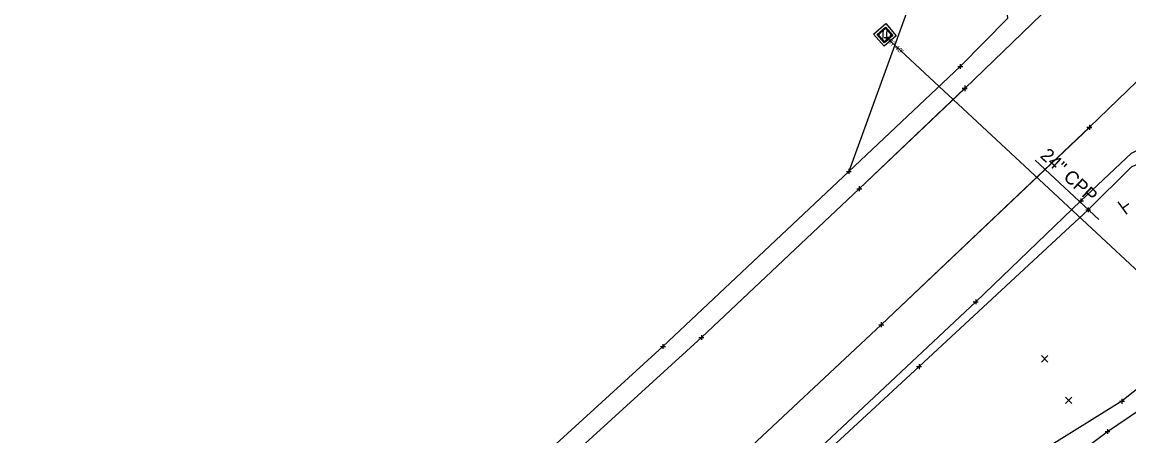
# Model space of a CAD drawing. Extents: x 236 to 155644, y 66 to 491728.
# Drawn here: x 147690.6 to 147919.6, y 487289.2 to 487374.8 of the extents above; entities that cross this region are included whole.
import ezdxf

# ---------------------------------------------------------------- set-up
doc = ezdxf.new("R2010")
doc.units = 0
for name, color, linetype in [('DR_X_Storm_Sewer', 7, 'Continuous'), ('DR_X_Text', 7, 'Continuous'), ('GE_X_Alignment', 7, 'Continuous'), ('PM_X_Edge_Line', 7, 'Continuous'), ('PV_X_EOP', 7, 'Continuous'), ('PV_X_Shoulder', 7, 'Continuous'), ('PV_X_Shoulder_Aggregate', 7, 'Continuous'), ('RD_X_Cells', 7, 'Continuous'), ('RD_X_RR_Cells', 7, 'Continuous'), ('RW_X_Esmt_LA', 7, 'Continuous'), ('SC_Scratch1', 7, 'Continuous'), ('SV_P_Mon_Cells_Set', 7, 'Continuous'), ('SV_X_Mon_Cells_Found', 7, 'Continuous'), ('SV_X_Shot_Marker', 7, 'Continuous'), ('SV_X_Terrain_Boundary', 7, 'Continuous')]:
    doc.layers.add(name, color=color, linetype=linetype)

msp = doc.modelspace()

# ---------------------------------------------------------------- linework, layer by layer
at = {"layer": 'DR_X_Storm_Sewer'}
msp.add_line((147869.46, 487371.63), (147938.02, 487307.8), dxfattribs=at)
at = {"layer": 'DR_X_Text'}
msp.add_line((147913.42, 487333.98), (147900.26, 487346.23), dxfattribs=at)
at = {"layer": 'GE_X_Alignment'}
for p, q in [((147919.29, 487335.04), (147917.38, 487337.61)), ((147918.34, 487336.32), (147919.62, 487337.28))]:
    msp.add_line(p, q, dxfattribs=at)
at = {"layer": 'PM_X_Edge_Line'}
for points in [[(147693.12, 487187.03), (147735.46, 487223.2), (147776.17, 487259.34), (147831.17, 487309.51), (147863.85, 487340.33), (147885.66, 487361.17)], [(147911.49, 487353.01), (147868.4, 487312.17), (147833.06, 487279.09), (147795.98, 487245.09), (147757.86, 487210.93), (147709.11, 487169.09)]]:
    msp.add_lwpolyline(points, dxfattribs=at)
at = {"layer": 'PV_X_EOP'}
for points in [[(147693.25, 487187.07), (147735.46, 487223.2), (147776.17, 487259.34), (147831.17, 487309.51), (147863.85, 487340.33), (147885.66, 487361.04), (147949.12, 487422.42), (147982.57, 487455.18), (148015.64, 487487.44), (148041.95, 487512.76)], [(148067.69, 487505.78), (148041.51, 487479.67), (148022.76, 487461.37), (148000.61, 487439.67), (147970.81, 487410.54), (147942.69, 487383.21), (147911.46, 487353.05), (147868.4, 487312.17), (147833.06, 487279.09), (147795.98, 487245.09), (147757.86, 487210.93), (147709.11, 487169.11)]]:
    msp.add_lwpolyline(points, dxfattribs=at)
at = {"layer": 'PV_X_Shoulder'}
for points in [[(147690.61, 487190.15), (147732.8, 487226.1), (147774.27, 487263.04), (147823.22, 487307.65), (147861.69, 487343.91), (147884.74, 487365.64), (147894.59, 487375.61), (147893.39, 487386.74), (147891.21, 487392.14), (147885.44, 487395.33), (147880.57, 487395.98)], [(147716.48, 487162.39), (147750.61, 487192.09), (147787.34, 487224.12), (147823.29, 487256.58), (147855.91, 487286.84), (147887.93, 487316.9), (147909.72, 487337.82), (147920.17, 487347.67), (147924.23, 487349.79), (147934.53, 487351.81), (147947.58, 487349.62), (147959.14, 487340.88), (147972.4, 487326.26), (147986.99, 487307.58), (147996.62, 487292.84), (148010.03, 487266.34), (148017.23, 487247.05)]]:
    msp.add_lwpolyline(points, dxfattribs=at)
at = {"layer": 'PV_X_Shoulder_Aggregate'}
msp.add_lwpolyline([(148012.53, 487250.31), (148003.26, 487274.09), (147989.7, 487297.58), (147980.31, 487311.09), (147966.57, 487328.17), (147956.32, 487337.98), (147948.04, 487345.7), (147936.67, 487349.15), (147928.99, 487348.9), (147920.13, 487344.77), (147911.2, 487335.96), (147876.2, 487303.5), (147840.82, 487270.78), (147803.73, 487236.95), (147764.71, 487202.62), (147718.33, 487161.2)], dxfattribs=at)
at = {"layer": 'RD_X_Cells'}
for p, q in [((147884.74, 487366.14), (147884.74, 487365.14)), ((147884.24, 487365.64), (147885.24, 487365.64)), ((147884.74, 487365.64), (147884.74, 487365.64)), ((147885.66, 487361.67), (147885.66, 487360.67)), ((147885.66, 487361.54), (147885.66, 487360.54)), ((147885.16, 487361.17), (147886.16, 487361.17)), ((147885.16, 487361.04), (147886.16, 487361.04)), ((147885.66, 487361.17), (147885.66, 487361.17)), ((147885.66, 487361.04), (147885.66, 487361.04)), ((147910.96, 487353.05), (147911.96, 487353.05)), ((147910.99, 487353.01), (147911.99, 487353.01)), ((147911.46, 487353.55), (147911.46, 487352.55)), ((147911.46, 487353.05), (147911.46, 487353.05)), ((147911.49, 487353.51), (147911.49, 487352.51)), ((147911.49, 487353.01), (147911.49, 487353.01)), ((147861.19, 487343.91), (147862.19, 487343.91)), ((147861.69, 487344.41), (147861.69, 487343.41)), ((147861.69, 487343.91), (147861.69, 487343.91)), ((147863.85, 487340.83), (147863.85, 487339.83)), ((147863.85, 487340.83), (147863.85, 487339.83)), ((147863.35, 487340.33), (147864.35, 487340.33)), ((147863.35, 487340.33), (147864.35, 487340.33)), ((147863.85, 487340.33), (147863.85, 487340.33)), ((147863.85, 487340.33), (147863.85, 487340.33)), ((147909.22, 487337.82), (147910.22, 487337.82)), ((147909.72, 487338.32), (147909.72, 487337.32)), ((147909.72, 487337.82), (147909.72, 487337.82)), ((147911.2, 487336.46), (147911.2, 487335.46)), ((147910.7, 487335.96), (147911.7, 487335.96)), ((147911.2, 487335.96), (147911.2, 487335.96)), ((147887.43, 487316.9), (147888.43, 487316.9)), ((147887.93, 487317.4), (147887.93, 487316.4)), ((147887.93, 487316.9), (147887.93, 487316.9)), ((147867.9, 487312.17), (147868.9, 487312.17)), ((147867.9, 487312.17), (147868.9, 487312.17)), ((147868.4, 487312.67), (147868.4, 487311.67)), ((147868.4, 487312.67), (147868.4, 487311.67)), ((147868.4, 487312.17), (147868.4, 487312.17)), ((147868.4, 487312.17), (147868.4, 487312.17)), ((147830.67, 487309.51), (147831.67, 487309.51)), ((147830.67, 487309.51), (147831.67, 487309.51)), ((147831.17, 487310.01), (147831.17, 487309.01)), ((147831.17, 487310.01), (147831.17, 487309.01)), ((147831.17, 487309.51), (147831.17, 487309.51)), ((147831.17, 487309.51), (147831.17, 487309.51)), ((147822.72, 487307.65), (147823.72, 487307.65)), ((147823.22, 487308.15), (147823.22, 487307.15)), ((147823.22, 487307.65), (147823.22, 487307.65)), ((147875.7, 487303.5), (147876.7, 487303.5)), ((147876.2, 487304), (147876.2, 487303)), ((147876.2, 487303.5), (147876.2, 487303.5)), ((147917.69, 487296.31), (147918.69, 487296.31)), ((147918.19, 487296.81), (147918.19, 487295.81)), ((147918.19, 487296.31), (147918.19, 487296.31)), ((147915.21, 487290.57), (147915.21, 487289.57)), ((147914.71, 487290.07), (147915.71, 487290.07)), ((147915.21, 487290.07), (147915.21, 487290.07))]:
    msp.add_line(p, q, dxfattribs=at)
at = {"layer": 'RD_X_RR_Cells'}
for p, q in [((147868.96, 487371.63), (147869.96, 487371.63)), ((147869.46, 487372.13), (147869.46, 487371.13)), ((147869.46, 487371.63), (147869.46, 487371.63))]:
    msp.add_line(p, q, dxfattribs=at)
at = {"layer": 'RW_X_Esmt_LA'}
for points in [[(147927.21, 487303.51), (147918.19, 487296.31), (147902.65, 487286.65), (147888.67, 487276.48), (147875.34, 487268.36), (147858.93, 487258.16)], [(147724.11, 487154.64), (147735.26, 487162.98), (147750.18, 487173.76), (147770.43, 487189.88), (147784.89, 487202.44), (147807.35, 487217.59), (147820.51, 487225.97), (147840.53, 487238.83), (147853.92, 487249.68), (147868.86, 487260.42), (147869.37, 487261.44), (147881.25, 487268.44), (147896.11, 487277.16), (147909.96, 487286.12), (147915.21, 487290.07), (147921.81, 487294.57), (147924.47, 487296.7), (147929.25, 487299.55)]]:
    msp.add_lwpolyline(points, dxfattribs=at)
at = {"layer": 'SV_P_Mon_Cells_Set'}
for p, q in [((147901.56, 487304.44), (147902.89, 487305.78)), ((147901.56, 487305.78), (147902.89, 487304.44)), ((147906.51, 487295.85), (147907.84, 487297.19)), ((147906.51, 487297.19), (147907.84, 487295.85))]:
    msp.add_line(p, q, dxfattribs=at)
at = {"layer": 'SV_X_Mon_Cells_Found'}
for p, q in [((147868.68, 487370.96), (147868.85, 487373.44)), ((147869.48, 487370.95), (147869.64, 487373.34)), ((147867.94, 487371.81), (147868, 487372.7)), ((147870.33, 487371.69), (147870.39, 487372.49))]:
    msp.add_line(p, q, dxfattribs=at)
for points in [[(147866.79, 487372.33), (147869.3, 487374.52), (147871.49, 487372.01), (147868.98, 487369.82)], [(147867.52, 487372.28), (147869.25, 487373.79), (147870.76, 487372.06), (147869.03, 487370.56)], [(147867.73, 487372.27), (147869.24, 487373.58), (147870.55, 487372.08), (147869.04, 487370.76)]]:
    msp.add_lwpolyline(points, close=True, dxfattribs=at)
at = {"layer": 'SV_X_Shot_Marker'}
for p, q in [((147868.04, 487373.43), (147868.04, 487373.43)), ((147868.48, 487372.93), (147868.48, 487372.93)), ((147868.39, 487371.52), (147868.39, 487371.52)), ((147869.14, 487372.17), (147869.14, 487372.17)), ((147869.14, 487372.17), (147869.14, 487372.17)), ((147869.14, 487372.17), (147869.14, 487372.17)), ((147869.8, 487371.42), (147869.8, 487371.42)), ((147869.89, 487372.83), (147869.89, 487372.83)), ((147870.23, 487370.92), (147870.23, 487370.92))]:
    msp.add_line(p, q, dxfattribs=at)
at = {"layer": 'SV_X_Terrain_Boundary'}
msp.add_lwpolyline([(147923.37, 487432.95), (147880.57, 487395.98), (147861.69, 487343.91), (147823.22, 487307.65), (147774.27, 487263.04), (147732.8, 487226.1), (147690.61, 487190.15)], dxfattribs=at)

# ---------------------------------------------------------------- texts
at = {"layer": 'DR_X_Text'}
msp.add_text('24" CPP', height=2.8, rotation=317.047, dxfattribs=at).set_placement((147901.1, 487346.96))
at = {"layer": 'SC_Scratch1'}
msp.add_text("897.48'", height=1, rotation=317.047, dxfattribs=at).set_placement((147869.12, 487371.26))

doc.saveas('drawing.dxf')
